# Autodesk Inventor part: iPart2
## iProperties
Shininess: 64.0
Length Units: 11269
Angle Units: 11279
Time Units: 11290
Mass Units: 11283
Length Display Precision: 3
Angle Display Precision: 2
Compacted: True
Part Number: iPart2
Document SubType Name: Modeling
Created: 2003-11
Designer: Owner
Manufacturer: Standard
Standards Organization: Custom
Density: 0.0
Volumn: 0.0
Area: 0.0
PropertySet Name: Model Information
Control State: 0
Master: False
Checked Out: False
Author: Owner
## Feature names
1. Extrusion1
2. Fillet1
